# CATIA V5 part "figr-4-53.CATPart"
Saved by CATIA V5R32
Part number: Part1
Material "Aluminium": density 2710 kg/m3, Young's modulus 7e+10 Pa, Poisson ratio 0.346, thermal expansion 2.36e-05 1/K
Bounding box of the stored display mesh (mm): x -69.981 to 69.981, y -240 to 0, z -69.908 to 69.908
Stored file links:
  D:\PROJECTS\Project 2022\CATIA V5 6R 2022\Resources\Part Files\c04_catia_v5_6r2022_prt\figr-4-53.CATPart
  C:\Program Files\Dassault Systemes\B32\win_b64\startup\materials\Catalog.CATMaterial
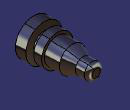
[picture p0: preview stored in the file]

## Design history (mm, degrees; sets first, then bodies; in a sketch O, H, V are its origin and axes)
Body1 (main body), material "Steel"
  Sketch1 on yz-plane, origin (0, 0, 0), H (0, 1, 0), V (0, 0, 1)
    line L1 (0, 0) -> (0, 15.359)
    arc A1 centre (-15.359, 15.359) radius 15.359 from (0, 15.359) to (-15.359, 30.718) ccw
    point P2 (-15.359, 15.359)
    line L2 (-15.359, 30.718) -> (-49.6877, 30.718)
    line L3 (-49.6877, 30.718) -> (-91.8922, 49.6007)
    line L4 (-91.8922, 49.6007) -> (-149.3038, 49.6007)
    line L5 (-149.3038, 49.6007) -> (-149.3038, 60)
    line L6 (-149.3038, 60) -> (-180, 60)
    line L7 (-180, 60) -> (-180, 38.9967)
    line L8 (-180, 38.9967) -> (-200, 40)
    line L9 (-200, 40) -> (-200, 70)
    line L10 (-200, 70) -> (-240, 70)
    line L11 (-240, 70) -> (-240, 0)
    line L12 (-240, 0) -> (0, 0)
    axis line L13 (-300, 0) -> (50, 0)
    vertical: L1 V, L5 V, L7 V, L9 V, L11 V
    tangency: A1 L1, L2 A1, L8 A1, L12 A1, L13 A1
    coincidence: L3 P2
    horizontal: L4 H, L6 H, L10 H, L2 H
    fix: L12
  Shaft1: profile Sketch1, axis Sketch1.H, angle 360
